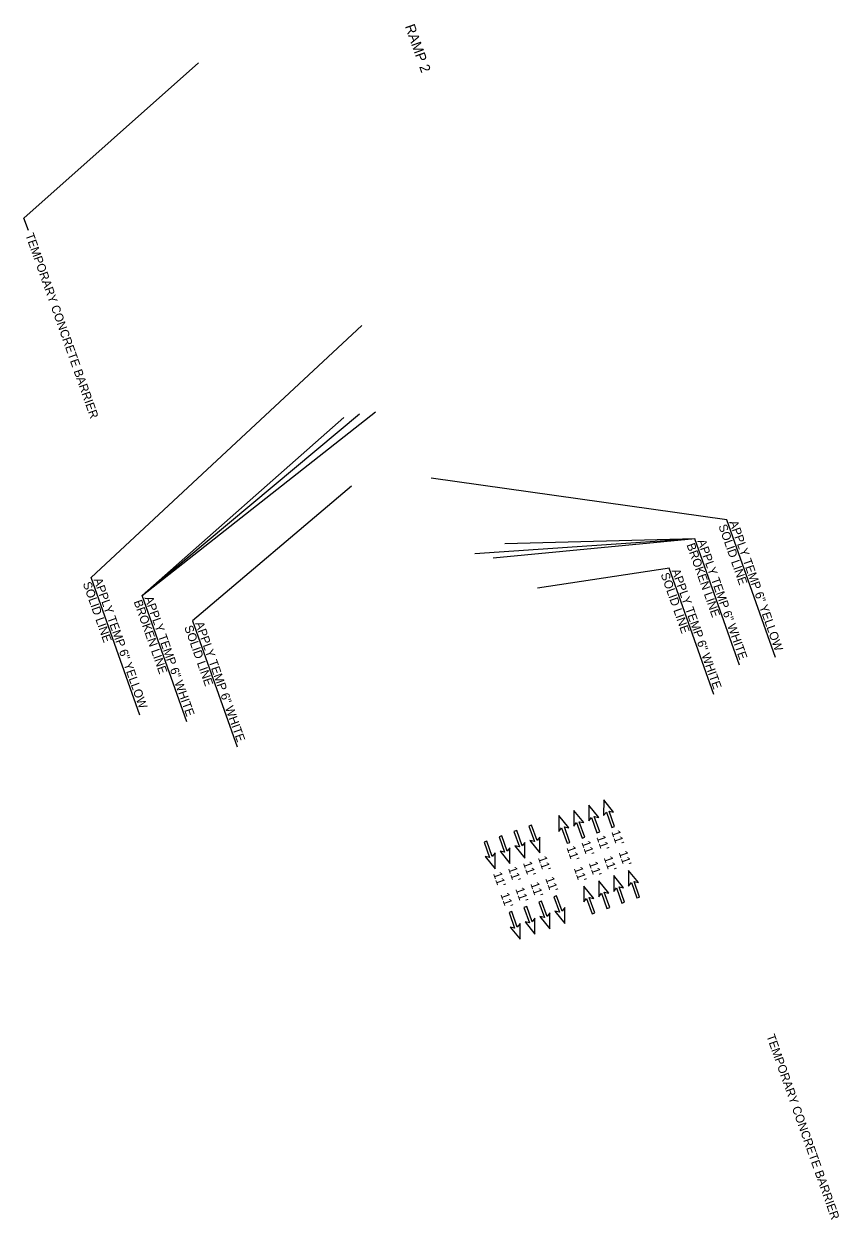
# Model space of a CAD drawing. Extents: x 2004770 to 2007199, y 1133765 to 1140032.
# Drawn here: x 2005818 to 2006383, y 1136125 to 1136955 of the extents above; entities that cross this region are included whole.
import ezdxf

# ---------------------------------------------------------------- set-up
doc = ezdxf.new("R2010")
doc.units = 0
doc.layers.add('RD_PD_MedBWall', color=7, linetype='Continuous')
doc.layers.add('RD_XS_Base', color=7, linetype='Continuous')

msp = doc.modelspace()

# ---------------------------------------------------------------- linework, layer by layer
at = {"layer": 'RD_PD_MedBWall'}
for p, q in [((2005900.1, 1136557.98), (2006062.09, 1136685.47)), ((2005900.1, 1136557.98), (2006050.93, 1136684.06)), ((2006339.5, 1136514.88), (2006305.67, 1136610.52)), ((2006283.58, 1136597.27), (2006143.65, 1136583.85)), ((2006283.58, 1136597.27), (2006151.78, 1136593.87)), ((2006314.53, 1136509.77), (2006283.54, 1136597.39)), ((2006296.62, 1136489.29), (2006265.63, 1136576.91)), ((2005898.64, 1136474.96), (2005864.8, 1136570.6)), ((2005931.1, 1136470.37), (2005900.1, 1136557.98)), ((2005966.19, 1136452.71), (2005935.19, 1136540.32))]:
    msp.add_line(p, q, dxfattribs=at)
for points in [[(2005821.24, 1136811.26), (2005818.16, 1136819.96), (2005939.29, 1136927.67)], [(2005864.8, 1136570.6), (2006052.58, 1136745.34)], [(2005900.1, 1136557.98), (2006040.1, 1136681.68)], [(2005935.04, 1136540.76), (2006045.24, 1136634.17)], [(2006305.67, 1136610.52), (2006100.67, 1136639.39)], [(2006283.1, 1136597.24), (2006130.85, 1136587.05)], [(2006265.88, 1136577), (2006174.32, 1136563.13)]]:
    msp.add_lwpolyline(points, dxfattribs=at)
for points in [[(2006215.58, 1136393.36), (2006217.47, 1136394.03), (2006213.69, 1136404.71), (2006216.76, 1136404.03), (2006209.86, 1136412.55), (2006209.85, 1136401.58), (2006211.81, 1136404.05)], [(2006225.95, 1136397.03), (2006227.84, 1136397.7), (2006224.06, 1136408.38), (2006227.13, 1136407.7), (2006220.23, 1136416.22), (2006220.22, 1136405.25), (2006222.18, 1136407.71)], [(2006194.84, 1136386.02), (2006196.73, 1136386.69), (2006192.95, 1136397.37), (2006196.02, 1136396.69), (2006189.12, 1136405.21), (2006189.11, 1136394.25), (2006191.06, 1136396.71)], [(2006205.21, 1136389.69), (2006207.1, 1136390.36), (2006203.32, 1136401.04), (2006206.39, 1136400.36), (2006199.49, 1136408.88), (2006199.48, 1136397.92), (2006201.43, 1136400.38)], [(2006159.89, 1136394.87), (2006158.01, 1136394.21), (2006161.79, 1136383.52), (2006158.72, 1136384.2), (2006165.62, 1136375.68), (2006165.63, 1136386.65), (2006163.67, 1136384.19)], [(2006170.26, 1136398.54), (2006168.38, 1136397.87), (2006172.16, 1136387.19), (2006169.09, 1136387.87), (2006175.99, 1136379.35), (2006176, 1136390.32), (2006174.04, 1136387.86)], [(2006139.15, 1136387.54), (2006137.27, 1136386.87), (2006141.05, 1136376.18), (2006137.98, 1136376.87), (2006144.88, 1136368.35), (2006144.89, 1136379.31), (2006142.93, 1136376.85)], [(2006149.52, 1136391.2), (2006147.64, 1136390.54), (2006151.42, 1136379.85), (2006148.35, 1136380.53), (2006155.25, 1136372.02), (2006155.26, 1136382.98), (2006153.3, 1136380.52)], [(2006222.53, 1136340.73), (2006224.42, 1136341.4), (2006220.64, 1136352.08), (2006223.71, 1136351.4), (2006216.81, 1136359.92), (2006216.8, 1136348.96), (2006218.75, 1136351.42)], [(2006232.9, 1136344.4), (2006234.79, 1136345.07), (2006231.01, 1136355.75), (2006234.08, 1136355.07), (2006227.18, 1136363.59), (2006227.17, 1136352.63), (2006229.12, 1136355.09)], [(2006243.27, 1136348.07), (2006245.16, 1136348.74), (2006241.38, 1136359.42), (2006244.45, 1136358.74), (2006237.55, 1136367.26), (2006237.54, 1136356.29), (2006239.5, 1136358.75)], [(2006212.16, 1136337.06), (2006214.05, 1136337.73), (2006210.27, 1136348.42), (2006213.34, 1136347.73), (2006206.44, 1136356.25), (2006206.43, 1136345.29), (2006208.38, 1136347.75)], [(2006177.21, 1136345.91), (2006175.33, 1136345.25), (2006179.11, 1136334.56), (2006176.04, 1136335.24), (2006182.94, 1136326.73), (2006182.95, 1136337.69), (2006180.99, 1136335.23)], [(2006187.58, 1136349.58), (2006185.7, 1136348.92), (2006189.48, 1136338.23), (2006186.41, 1136338.91), (2006193.31, 1136330.39), (2006193.32, 1136341.36), (2006191.36, 1136338.9)], [(2006156.47, 1136338.58), (2006154.59, 1136337.91), (2006158.37, 1136327.23), (2006155.3, 1136327.91), (2006162.2, 1136319.39), (2006162.21, 1136330.35), (2006160.25, 1136327.89)], [(2006166.84, 1136342.25), (2006164.96, 1136341.58), (2006168.74, 1136330.89), (2006165.67, 1136331.58), (2006172.57, 1136323.06), (2006172.58, 1136334.02), (2006170.62, 1136331.56)]]:
    msp.add_lwpolyline(points, close=True, dxfattribs=at)

# ---------------------------------------------------------------- texts
for s, p in [('TEMPORARY CONCRETE BARRIER', (2005819.08, 1136808.37)), ('APPLY TEMP 6" YELLOW', (2006307.28, 1136608.97)), ('SOLID LINE', (2006299.73, 1136606.3)), ('BROKEN LINE', (2006277.6, 1136593.17)), ('APPLY TEMP 6" WHITE', (2006285.15, 1136595.84)), ('APPLY TEMP 6" WHITE', (2006267.24, 1136575.36)), ('SOLID LINE', (2005858.87, 1136566.38)), ('APPLY TEMP 6" YELLOW', (2005866.41, 1136569.05)), ('SOLID LINE', (2006259.69, 1136572.69)), ('BROKEN LINE', (2005894.17, 1136553.76)), ('APPLY TEMP 6" WHITE', (2005901.71, 1136556.43)), ('SOLID LINE', (2005929.26, 1136536.1)), ('APPLY TEMP 6" WHITE', (2005936.8, 1136538.77)), ("11'", (2006225.51, 1136394)), ("11'", (2006204.77, 1136386.66)), ("11'", (2006215.14, 1136390.33)), ("11'", (2006174.6, 1136375.99)), ("11'", (2006194.4, 1136383)), ("11'", (2006220.22, 1136375.97)), ("11'", (2006230.59, 1136379.64)), ("11'", (2006153.86, 1136368.65)), ("11'", (2006164.23, 1136372.32)), ("11'", (2006199.48, 1136368.63)), ("11'", (2006209.85, 1136372.3)), ("11'", (2006143.49, 1136364.99)), ("11'", (2006179.68, 1136361.63)), ("11'", (2006148.57, 1136350.62)), ("11'", (2006158.94, 1136354.29)), ("11'", (2006169.31, 1136357.96)), ('TEMPORARY CONCRETE BARRIER', (2006333.01, 1136252.35))]:
    msp.add_text(s, height=6, rotation=289.48201, dxfattribs=at).set_placement(p)
at = {"layer": 'RD_XS_Base'}
msp.add_text('RAMP 2', height=7, rotation=289.48201, dxfattribs=at).set_placement((2006082.3, 1136953.13))

doc.saveas('drawing.dxf')
